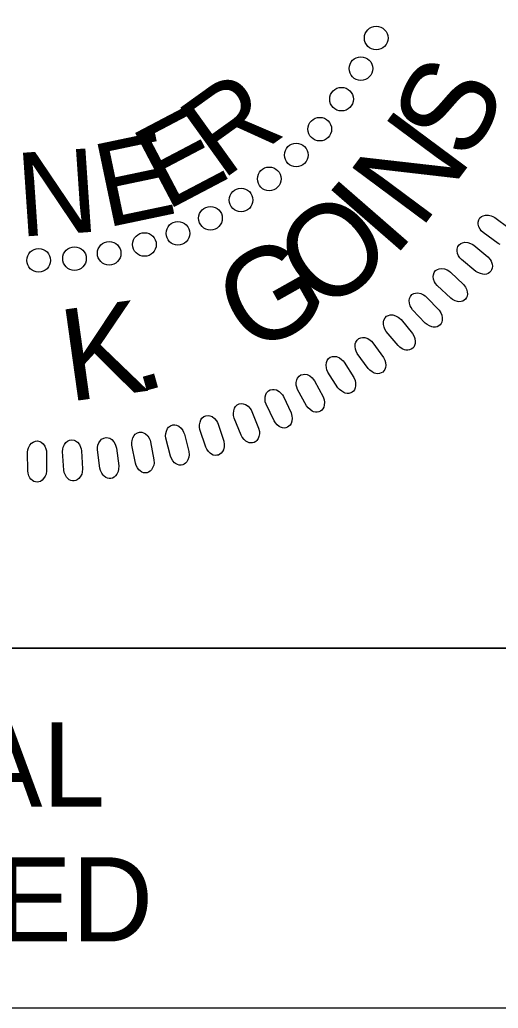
# Model space of a CAD drawing. Extents: x 18938 to 19565, y 6931 to 7973.
# Drawn here: x 19373.32 to 19377.54, y 7199.63 to 7208.34 of the extents above; entities that cross this region are included whole.
import ezdxf

# ---------------------------------------------------------------- set-up
doc = ezdxf.new("R2010")
doc.units = 0
for name, color, linetype in [('Old_Level_10', 7, 'Continuous'), ('Prop Pavement Schedule Description CELL', 7, 'Continuous'), ('Typical Hinge Slope Interstate CELL', 7, 'Continuous'), ('Typical Pavement Slope Information CELL', 7, 'Continuous')]:
    doc.layers.add(name, color=color, linetype=linetype)

# ---------------------------------------------------------------- blocks, each defined once
blk = doc.blocks.new('Gregory K. Goins')
at = {"layer": 'Old_Level_10'}
blk.add_lwpolyline([(-19.895, 27.386), (-20.037, 27.461), (-21.058, 28.194), (-21.182, 28.312), (-21.268, 28.431), (-21.345, 28.597), (-21.392, 28.77), (-21.399, 28.895), (-21.355, 29.058), (-21.283, 29.19), (-21.163, 29.287), (-21.061, 29.343), (-20.906, 29.388), (-20.698, 29.385), (-20.513, 29.333), (-20.391, 29.281), (-20.277, 29.217), (-19.286, 28.495)], dxfattribs=at)
for points in [[(-21.682, 27.336), (-20.737, 26.554), (-20.592, 26.386), (-20.517, 26.257), (-20.458, 26.062), (-20.436, 25.917), (-20.446, 25.779), (-20.482, 25.674), (-20.539, 25.574), (-20.625, 25.502), (-20.725, 25.428), (-20.837, 25.386), (-20.981, 25.369), (-21.081, 25.373), (-21.239, 25.417), (-21.415, 25.485), (-21.552, 25.57), (-22.525, 26.365), (-22.641, 26.491), (-22.72, 26.615), (-22.786, 26.785), (-22.822, 26.96), (-22.821, 27.086), (-22.768, 27.246), (-22.687, 27.373), (-22.561, 27.463), (-22.456, 27.511), (-22.299, 27.546), (-22.092, 27.53), (-21.91, 27.468), (-21.792, 27.408)], [(-23.277, 25.525), (-22.383, 24.685), (-22.248, 24.508), (-22.182, 24.374), (-22.135, 24.176), (-22.122, 24.03), (-22.141, 23.894), (-22.183, 23.791), (-22.246, 23.695), (-22.337, 23.627), (-22.441, 23.561), (-22.555, 23.525), (-22.7, 23.517), (-22.799, 23.528), (-22.955, 23.582), (-23.126, 23.661), (-23.258, 23.754), (-24.179, 24.609), (-24.287, 24.741), (-24.358, 24.87), (-24.413, 25.044), (-24.438, 25.221), (-24.429, 25.347), (-24.366, 25.503), (-24.277, 25.625), (-24.146, 25.706), (-24.038, 25.748), (-23.878, 25.773), (-23.673, 25.744), (-23.496, 25.67), (-23.381, 25.603)], [(-24.889, 23.832), (-24.049, 22.937), (-23.926, 22.751), (-23.869, 22.613), (-23.834, 22.413), (-23.83, 22.267), (-23.858, 22.132), (-23.906, 22.031), (-23.975, 21.94), (-24.07, 21.878), (-24.178, 21.818), (-24.295, 21.789), (-24.44, 21.791), (-24.538, 21.808), (-24.689, 21.871), (-24.856, 21.961), (-24.981, 22.062), (-25.847, 22.973), (-25.946, 23.112), (-26.009, 23.245), (-26.053, 23.422), (-26.067, 23.601), (-26.05, 23.726), (-25.977, 23.877), (-25.881, 23.993), (-25.745, 24.066), (-25.635, 24.102), (-25.474, 24.116), (-25.271, 24.075), (-25.098, 23.99), (-24.988, 23.916)], [(-26.621, 22.302), (-25.839, 21.356), (-25.728, 21.164), (-25.68, 21.023), (-25.658, 20.821), (-25.663, 20.674), (-25.699, 20.541), (-25.754, 20.444), (-25.828, 20.357), (-25.926, 20.302), (-26.038, 20.248), (-26.157, 20.227), (-26.301, 20.238), (-26.398, 20.26), (-26.545, 20.333), (-26.706, 20.434), (-26.825, 20.542), (-27.631, 21.506), (-27.721, 21.651), (-27.776, 21.787), (-27.808, 21.967), (-27.811, 22.146), (-27.787, 22.27), (-27.704, 22.416), (-27.602, 22.527), (-27.461, 22.591), (-27.348, 22.619), (-27.187, 22.623), (-26.987, 22.569), (-26.82, 22.473), (-26.715, 22.392)], [(-28.527, 20.736), (-27.807, 19.744), (-27.709, 19.544), (-27.668, 19.401), (-27.659, 19.198), (-27.674, 19.052), (-27.717, 18.921), (-27.779, 18.827), (-27.858, 18.746), (-27.96, 18.696), (-28.075, 18.65), (-28.194, 18.636), (-28.338, 18.656), (-28.433, 18.685), (-28.576, 18.767), (-28.729, 18.877), (-28.841, 18.992), (-29.586, 20.005), (-29.667, 20.156), (-29.712, 20.295), (-29.734, 20.477), (-29.725, 20.656), (-29.693, 20.777), (-29.602, 20.918), (-29.492, 21.022), (-29.347, 21.077), (-29.234, 21.099), (-29.072, 21.093), (-28.876, 21.026), (-28.715, 20.92), (-28.616, 20.833)], [(-30.472, 19.408), (-29.815, 18.372), (-29.729, 18.167), (-29.698, 18.021), (-29.702, 17.818), (-29.725, 17.673), (-29.777, 17.545), (-29.843, 17.455), (-29.928, 17.378), (-30.033, 17.336), (-30.15, 17.297), (-30.271, 17.291), (-30.412, 17.319), (-30.506, 17.355), (-30.643, 17.445), (-30.79, 17.565), (-30.894, 17.687), (-31.573, 18.744), (-31.645, 18.9), (-31.682, 19.042), (-31.691, 19.224), (-31.672, 19.402), (-31.632, 19.522), (-31.532, 19.657), (-31.416, 19.754), (-31.268, 19.8), (-31.153, 19.814), (-30.993, 19.798), (-30.801, 19.718), (-30.648, 19.603), (-30.554, 19.509)], [(-32.49, 18.152), (-31.9, 17.077), (-31.827, 16.867), (-31.805, 16.719), (-31.822, 16.516), (-31.854, 16.373), (-31.914, 16.249), (-31.987, 16.164), (-32.076, 16.093), (-32.183, 16.056), (-32.302, 16.025), (-32.423, 16.027), (-32.562, 16.064), (-32.653, 16.105), (-32.785, 16.204), (-32.924, 16.333), (-33.02, 16.461), (-33.631, 17.559), (-33.693, 17.719), (-33.721, 17.863), (-33.719, 18.045), (-33.689, 18.222), (-33.642, 18.339), (-33.533, 18.467), (-33.411, 18.557), (-33.261, 18.593), (-33.145, 18.6), (-32.986, 18.574), (-32.8, 18.483), (-32.654, 18.358), (-32.566, 18.258)], [(-34.592, 17.088), (-34.07, 15.978), (-34.011, 15.764), (-33.998, 15.616), (-34.027, 15.414), (-34.069, 15.274), (-34.137, 15.154), (-34.214, 15.073), (-34.308, 15.007), (-34.417, 14.978), (-34.538, 14.954), (-34.658, 14.963), (-34.795, 15.009), (-34.884, 15.056), (-35.008, 15.162), (-35.139, 15.3), (-35.227, 15.434), (-35.768, 16.569), (-35.82, 16.731), (-35.839, 16.877), (-35.825, 17.059), (-35.783, 17.233), (-35.729, 17.347), (-35.613, 17.468), (-35.486, 17.55), (-35.334, 17.577), (-35.218, 17.576), (-35.061, 17.541), (-34.88, 17.438), (-34.742, 17.304), (-34.661, 17.199)], [(-36.72, 16.081), (-36.269, 14.94), (-36.223, 14.723), (-36.22, 14.574), (-36.262, 14.375), (-36.312, 14.237), (-36.387, 14.122), (-36.469, 14.046), (-36.567, 13.986), (-36.678, 13.964), (-36.8, 13.948), (-36.92, 13.964), (-37.053, 14.019), (-37.139, 14.071), (-37.256, 14.186), (-37.377, 14.33), (-37.457, 14.47), (-37.926, 15.636), (-37.968, 15.802), (-37.977, 15.949), (-37.953, 16.13), (-37.9, 16.301), (-37.839, 16.411), (-37.716, 16.525), (-37.583, 16.598), (-37.43, 16.616), (-37.313, 16.607), (-37.159, 16.562), (-36.986, 16.448), (-36.856, 16.306), (-36.782, 16.197)], [(-39.012, 15.222), (-38.634, 14.056), (-38.602, 13.836), (-38.608, 13.687), (-38.662, 13.49), (-38.721, 13.356), (-38.803, 13.246), (-38.89, 13.176), (-38.991, 13.122), (-39.103, 13.107), (-39.226, 13.098), (-39.344, 13.122), (-39.474, 13.185), (-39.556, 13.243), (-39.666, 13.364), (-39.779, 13.517), (-39.849, 13.661), (-40.244, 14.854), (-40.275, 15.022), (-40.275, 15.169), (-40.24, 15.348), (-40.176, 15.515), (-40.108, 15.622), (-39.977, 15.727), (-39.841, 15.792), (-39.687, 15.8), (-39.572, 15.785), (-39.42, 15.73), (-39.255, 15.605), (-39.135, 15.455), (-39.066, 15.342)], [(-41.304, 14.551), (-40.999, 13.362), (-40.981, 13.141), (-40.997, 12.993), (-41.063, 12.8), (-41.13, 12.67), (-41.219, 12.565), (-41.31, 12.5), (-41.415, 12.454), (-41.528, 12.445), (-41.651, 12.444), (-41.767, 12.475), (-41.894, 12.547), (-41.971, 12.609), (-42.074, 12.737), (-42.176, 12.896), (-42.237, 13.045), (-42.557, 14.26), (-42.577, 14.43), (-42.568, 14.577), (-42.521, 14.754), (-42.447, 14.916), (-42.373, 15.018), (-42.236, 15.115), (-42.095, 15.172), (-41.941, 15.17), (-41.827, 15.147), (-41.679, 15.083), (-41.522, 14.948), (-41.411, 14.791), (-41.35, 14.673)], [(-50.637, 13.286), (-50.638, 12.059), (-50.676, 11.841), (-50.728, 11.7), (-50.84, 11.531), (-50.937, 11.421), (-51.05, 11.341), (-51.154, 11.302), (-51.266, 11.282), (-51.378, 11.302), (-51.498, 11.332), (-51.603, 11.391), (-51.707, 11.492), (-51.767, 11.571), (-51.834, 11.721), (-51.894, 11.9), (-51.916, 12.06), (-51.923, 13.316), (-51.901, 13.486), (-51.856, 13.626), (-51.766, 13.785), (-51.654, 13.925), (-51.556, 14.005), (-51.4, 14.064), (-51.25, 14.084), (-51.101, 14.044), (-50.996, 13.994), (-50.868, 13.895), (-50.75, 13.725), (-50.682, 13.545), (-50.653, 13.416)], [(-48.27, 13.409), (-48.194, 12.184), (-48.217, 11.963), (-48.26, 11.82), (-48.362, 11.644), (-48.452, 11.528), (-48.559, 11.442), (-48.661, 11.396), (-48.772, 11.369), (-48.884, 11.382), (-49.006, 11.404), (-49.114, 11.457), (-49.225, 11.551), (-49.29, 11.626), (-49.366, 11.772), (-49.437, 11.947), (-49.469, 12.105), (-49.556, 13.358), (-49.544, 13.529), (-49.507, 13.671), (-49.427, 13.836), (-49.325, 13.982), (-49.232, 14.068), (-49.08, 14.138), (-48.932, 14.167), (-48.78, 14.136), (-48.673, 14.093), (-48.539, 14.002), (-48.41, 13.84), (-48.331, 13.664), (-48.293, 13.537)], [(-45.905, 13.603), (-45.752, 12.385), (-45.761, 12.163), (-45.795, 12.018), (-45.885, 11.835), (-45.968, 11.715), (-46.07, 11.621), (-46.168, 11.569), (-46.278, 11.535), (-46.391, 11.541), (-46.513, 11.556), (-46.624, 11.602), (-46.741, 11.688), (-46.81, 11.759), (-46.896, 11.9), (-46.978, 12.07), (-47.02, 12.226), (-47.184, 13.471), (-47.183, 13.642), (-47.156, 13.787), (-47.087, 13.956), (-46.994, 14.108), (-46.907, 14.2), (-46.759, 14.279), (-46.612, 14.317), (-46.459, 14.296), (-46.349, 14.26), (-46.211, 14.177), (-46.072, 14.024), (-45.982, 13.854), (-45.936, 13.729)], [(-43.59, 14.013), (-43.361, 12.808), (-43.356, 12.586), (-43.381, 12.439), (-43.459, 12.251), (-43.535, 12.125), (-43.63, 12.025), (-43.725, 11.967), (-43.832, 11.927), (-43.945, 11.926), (-44.068, 11.932), (-44.183, 11.971), (-44.304, 12.05), (-44.378, 12.117), (-44.472, 12.251), (-44.564, 12.416), (-44.616, 12.569), (-44.859, 13.802), (-44.868, 13.972), (-44.85, 14.119), (-44.792, 14.291), (-44.709, 14.45), (-44.627, 14.547), (-44.485, 14.634), (-44.341, 14.682), (-44.187, 14.67), (-44.075, 14.641), (-43.931, 14.567), (-43.782, 14.423), (-43.682, 14.259), (-43.629, 14.138)]]:
    blk.add_lwpolyline(points, close=True, dxfattribs=at)
for centre in [(-28.304, 41.38), (-29.34, 39.309), (-30.654, 37.238), (-32.128, 35.206), (-33.721, 33.454), (-35.55, 31.838), (-37.462, 30.405), (-39.533, 29.17), (-41.739, 28.148), (-44.009, 27.392), (-46.398, 26.795), (-51.176, 26.318), (-48.747, 26.437)]:
    blk.add_circle(centre, 0.801, dxfattribs=at)
for s, height, rotation, p in [('S', 6.236, 62.87249, (-21.932, 32.885)), ('R', 5.669, 35.66356, (-38.772, 31.701)), ('E', 5.669, 27.72376, (-42.553, 29.639)), ('N', 6.236, 53.3828, (-25.319, 28.324)), ('E', 5.669, 11.84417, (-46.623, 28.516)), ('N', 5.669, 3.90437, (-52.471, 27.91)), ('I', 6.236, 48.95519, (-27.148, 26.402)), ('O', 6.236, 38.85534, (-31.835, 22.583)), ('G', 6.236, 29.36565, (-36.785, 19.796)), ('K', 6.236, 7.95864, (-49.166, 16.726)), ('.', 6.236, 15.66304, (-44.587, 17.294))]:
    blk.add_text(s, height=height, rotation=rotation, dxfattribs=at).set_placement(p)

msp = doc.modelspace()

# ---------------------------------------------------------------- linework, layer by layer
at = {"layer": 'Typical Hinge Slope Interstate CELL'}
for p, q in [((19353.1353, 7202.8026), (19380.142, 7202.8026)), ((19380.142, 7199.63), (19353.1353, 7199.63))]:
    msp.add_line(p, q, dxfattribs=at)
at = {"layer": 'Typical Pavement Slope Information CELL'}
msp.add_lwpolyline([(19366.642, 7217.8472), (19380.142, 7217.8472), (19380.142, 7202.8026), (19366.642, 7202.8026)], close=True, dxfattribs=at)

# ---------------------------------------------------------------- block references
at = {"layer": 'Prop Pavement Schedule Description CELL', "xscale": 0.13, "yscale": 0.13}
msp.add_blockref('Gregory K. Goins', (19380.142, 7202.796), dxfattribs=at)

# ---------------------------------------------------------------- texts
at = {"layer": 'Typical Hinge Slope Interstate CELL'}
for s, p in [('DOCUMENT NOT CONSIDERED FINAL', (19355.98, 7201.4059)), ('UNLESS ALL SIGNATURES COMPLETED', (19355.2954, 7200.2179))]:
    msp.add_text(s, height=0.742545, dxfattribs=at).set_placement(p)

doc.saveas('drawing.dxf')
